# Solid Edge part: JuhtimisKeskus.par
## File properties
Author: Egon 815
Template: Normal.par
Last saved by: Egon 815
Revision: 6
Application: Solid Edge
Accuracy: 0,990
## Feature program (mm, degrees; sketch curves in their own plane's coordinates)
sketch for "unnamed Protrusion 1" plane through (0, 0, 10563.589) normal (0, 0, 1) x-axis (1, 0, 0)
  arc centre (50312.6386, -44736.8538) radius 46315.7343 from (4900.7754, -35631.365) to (8107.6748, -25660.9979) cw
  arc centre (2089.3841, -22290.9852) radius 6897.5945 from (8107.6748, -25660.9979) to (8107.6748, -18920.9725) ccw
  line (8107.6748, -13839.988) -> (8107.6748, -18920.9725)
  line (8107.6748, -13839.988) -> (0, -13839.988)
  line (-8107.6748, -13839.988) -> (0, -13839.988)
  line (-8107.6748, -18920.9725) -> (-8107.6748, -13839.988)
  arc centre (-2089.3841, -22290.9852) radius 6897.5945 from (-8107.6748, -25660.9979) to (-8107.6748, -18920.9725) cw
  arc centre (-50312.6386, -44736.8538) radius 46315.7343 from (-4900.7754, -35631.365) to (-8107.6748, -25660.9979) ccw
  arc centre (60.6073, -34547.8525) radius 5078.3183 from (-4900.7754, -35631.365) to (0, -39625.8092) ccw
  arc centre (-60.6073, -34547.8525) radius 5078.3183 from (4900.7754, -35631.365) to (0, -39625.8092) cw
extrude "unnamed Protrusion 1" add to key point along +normal
sketch for "unnamed Protrusion 2" plane through (0, -26732.8986, 13000.7205) normal (0, 0, 1) x-axis (1, 0, 0)
  circle centre (0, -8026.2647) radius 4634.2784
extrude "unnamed Protrusion 2" add to key point along +normal
sketch for "unnamed Protrusion 3" plane through (0, -34759.1633, 17243.6107) normal (0, 0, 1) x-axis (0, 1, 0)
  line (-4971.8461, -5486.8125) -> (2928.4356, -5486.8125)
  line (5915.7039, -5486.8125) -> (2928.4356, -5486.8125)
  line (5915.7039, 0) -> (5915.7039, -5486.8125)
  line (5915.7039, 0) -> (5915.7039, 5486.8125)
  line (5915.7039, 5486.8125) -> (2928.4356, 5486.8125)
  line (-4971.8461, 5486.8125) -> (2928.4356, 5486.8125)
  line (-6335.4528, 3406.3628) -> (-4971.8461, 5486.8125)
  line (-6335.4528, 0) -> (-6335.4528, 3406.3628)
  line (-6335.4528, 0) -> (-6335.4528, -3406.3628)
  line (-6335.4528, -3406.3628) -> (-4971.8461, -5486.8125)
extrude "unnamed Protrusion 3" add to key point along +normal
sketch for "unnamed Protrusion 4" plane through (0, -34969.0377, 22633.8218) normal (0, 0, 1) x-axis (0, 1, 0)
  circle centre (3866.8289, 0) radius 993.7379
extrude "unnamed Protrusion 4" add to key point along +normal
sketch for "unnamed Protrusion 5" plane through (0, -34969.0377, 22633.8218) normal (0, 0, 1) x-axis (0, 1, 0)
  arc centre (-838.8517, 156.2684) radius 1969.9228 from (-838.8517, 2126.1912) to (-2802.6619, 311.3349) ccw
  line (-2802.6619, 0) -> (-2802.6619, 311.3349)
  line (-2802.6619, 0) -> (-2802.6619, -311.3349)
  arc centre (-838.8517, -156.2684) radius 1969.9228 from (-838.8517, -2126.1912) to (-2802.6619, -311.3349) cw
  line (-838.8517, -2126.1912) -> (1157.986, -2126.1912)
  line (1157.986, -2126.1912) -> (1157.986, 0)
  line (1157.986, 2126.1912) -> (1157.986, 0)
  line (-838.8517, 2126.1912) -> (1157.986, 2126.1912)
extrude "unnamed Protrusion 5" add to key point along +normal
chamfer "unnamed Chamfer 1"
lofted protrusion "unnamed LoftedProtrusion 1"
chamfer "Chamfer_2" setback 500
chamfer "Chamfer_3" setback 100
chamfer "Chamfer_4" setback 100
chamfer "Chamfer_5" setback 100
chamfer "Chamfer_6" setback 500
chamfer "Chamfer_7" setback 500
chamfer "Chamfer_8" setback 500
logasc func "Lip_Groove_1"  LipOrGrooveWidth = 60 mm; LipOrGrooveHeight = 1000 mm
sketch for "ExtrudedProtrusion_6" plane through (0, -31102.2088, 30853.7571) normal (0, 0, 1) x-axis (0, 1, 0)
  arc centre (-4395.8563, 11697.9012) radius 9102.8237 from (-4402.7394, 2595.0801) to (1141.8911, 4473.3075) ccw
  arc centre (961.8585, 0) radius 4476.9288 from (1141.8911, 4473.3075) to (1141.8911, -4473.3075) cw
  arc centre (-4395.8563, -11697.9012) radius 9102.8237 from (-4402.7394, -2595.0801) to (1141.8911, -4473.3075) cw
  arc centre (-4402.7394, 0) radius 2595.0801 from (-6997.8195, 0) to (-4402.7394, -2595.0801) ccw
extrude "ExtrudedProtrusion_6" add finite 60 along +normal
logasc func "Lip_Groove_4"  LipOrGrooveWidth = 60 mm; LipOrGrooveHeight = 1000 mm
sketch for "unnamed RevolvedProtrusion 1" plane through (0, 0, 0) normal (1, 0, 0) x-axis (0, 1, 0)
  arc centre (-27564.0235, 39353.1178) radius 6027.8587 from (-30944.9145, 34362.6613) to (-26080.3504, 33510.7044) ccw
  line (-26080.3504, 33510.7044) -> (-26080.3504, 33411.8659)
  arc centre (-27553.9133, 39428.8527) radius 6194.7976 from (-31012.9057, 34289.7001) to (-26080.3504, 33411.8659) ccw
  line (-30944.9145, 34362.6613) -> (-31012.9057, 34289.7001)
revolve "unnamed RevolvedProtrusion 1" add finite 360 deg
web network "WebNetwork_1"  Thickness = 0.25 mm
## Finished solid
Body 1: solid body, 99 faces, 233 edges, 141 vertices, 1 internal void.
  Faces by surface: plane 54, cylinder 26, cone 8, spline 8, torus 3
  Edges by curve: line 129, circle 63, curve on surface 29, intersection 10, ellipse 1, spline 1
Bounding box of the edges (mm; curved faces can reach further): 17973.957 x 27254.628 x 28591.551, from (-8986.9785, -41094.6161, 10563.589) to (8986.9785, -13839.988, 39155.1399).
Cylindrical faces by radius (mm): R249.875 x1, R250.125 x1, R993.7379 x1, R1969.9228 x2, R2535.0801 x1, R2595.0801 x1, R4416.9288 x1, R4476.9288 x1, R4634.2784 x1, R5018.3183 x2, R5078.3183 x2, R6837.5945 x2, R6897.5945 x2, R9102.8237 x2, R9162.8237 x2, R46315.7343 x2, R46375.7343 x2
Conical faces (half-angle, radius in mm at the cone's reference point): 42.9806 deg R4139.6619 x1, 45 deg R1093.7379 x1, 45 deg R1969.9228 x2, 45 deg R4634.2784 x1, 45 deg R5134.2784 x3
Toroidal faces (ring radius, tube radius in mm): R-973.076 r6194.7976 x2, R-928.8401 r6027.8587 x1
Planar faces by outward normal: +x 4, +y 3, +z 7, -x 4, -y 3, -z 5, oblique 28
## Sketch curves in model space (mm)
circle centre (0, -29017.8119, 30913.7571) radius 250
line (0, -26080.3504, 33510.7044) -> (0, -26080.3504, 33411.8659)
arc centre (0, -27553.9133, 39428.8527) radius 6194.7976 from (0, -31012.9057, 34289.7001) through (0, -28639.3307, 33329.8867) to (0, -26080.3504, 33411.8659)
line (0, -30944.9145, 34362.6613) -> (0, -31012.9057, 34289.7001)
arc centre (0, -27564.0235, 39353.1178) radius 6027.8587 from (0, -30944.9145, 34362.6613) through (0, -28603.8872, 33415.6298) to (0, -26080.3504, 33510.7044)
arc centre (-11697.9012, -35498.0651, 30853.7571) radius 9102.8237 from (-2595.0801, -35504.9482, 30853.7571) through (-3076.3091, -32577.5259, 30853.7571) to (-4473.3075, -29960.3177, 30853.7571)
arc centre (0, -30140.3503, 30853.7571) radius 4476.9288 from (-4473.3075, -29960.3177, 30853.7571) through (263.3964, -25671.1766, 30853.7571) to (4473.3075, -29960.3177, 30853.7571)
arc centre (11697.9012, -35498.0651, 30853.7571) radius 9102.8237 from (2595.0801, -35504.9482, 30853.7571) through (3076.3091, -32577.5259, 30853.7571) to (4473.3075, -29960.3177, 30853.7571)
arc centre (0, -35504.9482, 30853.7571) radius 2595.0801 from (0, -38100.0283, 30853.7571) through (1887.5928, -37285.8002, 30853.7571) to (2595.0801, -35504.9482, 30853.7571)
arc centre (0, -35504.9482, 30853.7571) radius 2595.0801 from (0, -38100.0283, 30853.7571) through (-1887.5928, -37285.8002, 30853.7571) to (-2595.0801, -35504.9482, 30853.7571)
line (0, -37464.9383, 30853.7571) -> (1920.1047, -37464.9383, 30853.7571)
line (0, -36553.8811, 30853.7571) -> (2354.4419, -36553.8811, 30853.7571)
line (0, -26589.1925, 30853.7571) -> (2345.2536, -26589.1925, 30853.7571)
line (1623.0423, -35623.699, 30853.7571) -> (1930.069, -35623.699, 30853.7571)
arc centre (-86.6061, -34579.2579, 30853.7571) radius 2003.4357 from (1623.0423, -35623.699, 30853.7571) through (931.0643, -36304.9756, 30853.7571) to (0, -36580.8208, 30853.7571)
arc centre (86.6061, -34579.2579, 30853.7571) radius 2003.4357 from (-1623.0423, -35623.699, 30853.7571) through (-931.0643, -36304.9756, 30853.7571) to (0, -36580.8208, 30853.7571)
line (-1623.0423, -35623.699, 30853.7571) -> (-1930.069, -35623.699, 30853.7571)
arc centre (-141.854, -35623.699, 30853.7571) radius 1788.215 from (-1930.069, -35623.699, 30853.7571) through (-1418.3424, -36876.013, 30853.7571) to (-282.6171, -37406.3652, 30853.7571)
line (-282.6171, -37406.3652, 30853.7571) -> (282.6171, -37406.3652, 30853.7571)
arc centre (141.854, -35623.699, 30853.7571) radius 1788.215 from (282.6171, -37406.3652, 30853.7571) through (1490.7635, -36797.648, 30853.7571) to (1930.069, -35623.699, 30853.7571)
arc centre (156.2684, -35807.8895, 25923.1734) radius 1969.9228 from (311.3349, -37771.6996, 25923.1734) through (1642.246, -37101.1281, 25923.1734) to (2126.1912, -35807.8895, 25923.1734)
line (1787.9662, -35807.8895, 25923.1734) -> (2126.1912, -35807.8895, 25923.1734)
arc centre (-95.4064, -34657.3185, 25923.1734) radius 2207.013 from (1787.9662, -35807.8895, 25923.1734) through (1025.6736, -36558.3934, 25923.1734) to (0, -36862.2683, 25923.1734)
arc centre (95.4064, -34657.3185, 25923.1734) radius 2207.013 from (-1787.9662, -35807.8895, 25923.1734) through (-1025.6736, -36558.3934, 25923.1734) to (0, -36862.2683, 25923.1734)
line (-1787.9662, -35807.8895, 25923.1734) -> (-2126.1912, -35807.8895, 25923.1734)
arc centre (-156.2684, -35807.8895, 25923.1734) radius 1969.9228 from (-2126.1912, -35807.8895, 25923.1734) through (-1562.4659, -37187.4561, 25923.1734) to (-311.3349, -37771.6996, 25923.1734)
line (-311.3349, -37771.6996, 25923.1734) -> (311.3349, -37771.6996, 25923.1734)
arc centre (156.2684, -35807.8895, 22633.8218) radius 1969.9228 from (2126.1912, -35807.8895, 22633.8218) through (1562.4659, -37187.4561, 22633.8218) to (311.3349, -37771.6996, 22633.8218)
line (2126.1912, -35807.8895, 22633.8218) -> (2126.1912, -33811.0517, 22633.8218)
line (2126.1912, -33811.0517, 22633.8218) -> (0, -33811.0517, 22633.8218)
line (-2126.1912, -33811.0517, 22633.8218) -> (0, -33811.0517, 22633.8218)
line (-2126.1912, -35807.8895, 22633.8218) -> (-2126.1912, -33811.0517, 22633.8218)
arc centre (-156.2684, -35807.8895, 22633.8218) radius 1969.9228 from (-2126.1912, -35807.8895, 22633.8218) through (-1562.4659, -37187.4561, 22633.8218) to (-311.3349, -37771.6996, 22633.8218)
line (0, -37771.6996, 22633.8218) -> (-311.3349, -37771.6996, 22633.8218)
line (0, -37771.6996, 22633.8218) -> (311.3349, -37771.6996, 22633.8218)
circle centre (0, -31102.2088, 22633.8218) radius 993.7379
line (3406.3628, -41094.6161, 17243.6107) -> (5486.8125, -39731.0094, 17243.6107)
line (5486.8125, -39731.0094, 17243.6107) -> (5486.8125, -31830.7277, 17243.6107)
line (5486.8125, -28843.4594, 17243.6107) -> (5486.8125, -31830.7277, 17243.6107)
line (0, -28843.4594, 17243.6107) -> (5486.8125, -28843.4594, 17243.6107)
line (0, -28843.4594, 17243.6107) -> (-5486.8125, -28843.4594, 17243.6107)
line (-5486.8125, -28843.4594, 17243.6107) -> (-5486.8125, -31830.7277, 17243.6107)
line (-5486.8125, -39731.0094, 17243.6107) -> (-5486.8125, -31830.7277, 17243.6107)
line (-3406.3628, -41094.6161, 17243.6107) -> (-5486.8125, -39731.0094, 17243.6107)
line (0, -41094.6161, 17243.6107) -> (-3406.3628, -41094.6161, 17243.6107)
line (0, -41094.6161, 17243.6107) -> (3406.3628, -41094.6161, 17243.6107)
circle centre (0, -34759.1633, 13000.7205) radius 4634.2784
arc centre (60.6073, -34547.8525, 10563.589) radius 5078.3183 from (-4900.7754, -35631.365, 10563.589) through (-3031.4665, -38576.301, 10563.589) to (0, -39625.8092, 10563.589)
arc centre (-50312.6386, -44736.8538, 10563.589) radius 46315.7343 from (-4900.7754, -35631.365, 10563.589) through (-6221.4927, -30555.2426, 10563.589) to (-8107.6748, -25660.9979, 10563.589)
arc centre (-2089.3841, -22290.9852, 10563.589) radius 6897.5945 from (-8107.6748, -25660.9979, 10563.589) through (-8986.9785, -22290.9852, 10563.589) to (-8107.6748, -18920.9725, 10563.589)
line (-8107.6748, -18920.9725, 10563.589) -> (-8107.6748, -13839.988, 10563.589)
line (-8107.6748, -13839.988, 10563.589) -> (0, -13839.988, 10563.589)
line (8107.6748, -13839.988, 10563.589) -> (0, -13839.988, 10563.589)
line (8107.6748, -13839.988, 10563.589) -> (8107.6748, -18920.9725, 10563.589)
arc centre (2089.3841, -22290.9852, 10563.589) radius 6897.5945 from (8107.6748, -25660.9979, 10563.589) through (8986.9785, -22290.9852, 10563.589) to (8107.6748, -18920.9725, 10563.589)
arc centre (50312.6386, -44736.8538, 10563.589) radius 46315.7343 from (4900.7754, -35631.365, 10563.589) through (6221.4927, -30555.2426, 10563.589) to (8107.6748, -25660.9979, 10563.589)
arc centre (-60.6073, -34547.8525, 10563.589) radius 5078.3183 from (4900.7754, -35631.365, 10563.589) through (3031.4665, -38576.301, 10563.589) to (0, -39625.8092, 10563.589)
line (-4658.2982, 0, 17061.7126) -> (-4658.2982, 0, 22614.5062)
line (-4658.2982, 0, 22614.5062) -> (4630.011, 0, 22614.5062)
line (4630.011, 0, 22614.5062) -> (4630.011, 0, 17061.7126)
line (4630.011, 0, 17061.7126) -> (-4658.2982, 0, 17061.7126)
line (-2437.1808, 0, 27536.3004) -> (2358.4137, 0, 27536.3004)
line (2358.4137, 0, 27536.3004) -> (2358.4137, 0, 22614.5062)
line (-2437.1808, 0, 22614.5062) -> (2358.4137, 0, 22614.5062)
line (-2437.1808, 0, 22614.5062) -> (-2437.1808, 0, 27536.3004)
line (-1478.0619, 0, 31221.3362) -> (1575.9746, 0, 31221.3362)
line (1575.9746, 0, 31221.3362) -> (1575.9746, 0, 27536.3004)
line (-1478.0619, 0, 27536.3004) -> (1575.9746, 0, 27536.3004)
line (-1478.0619, 0, 27536.3004) -> (-1478.0619, 0, 31221.3362)
line (0, -36553.8811, 30853.7571) -> (0, -36553.8811, 25923.1734)
line (0, -37771.6996, 22633.8218) -> (0, -37771.6996, 25923.1734)
line (0, -37464.9383, 30853.7571) -> (0, -37771.6996, 25923.1734)
line (0, -28843.4594, 17243.6107) -> (0, -28843.4594, 10563.589)
line (0, -39625.8092, 17243.6107) -> (0, -28843.4594, 17243.6107)
line (0, -28843.4594, 10563.589) -> (0, -39625.8092, 10563.589)
line (0, -39625.8092, 10563.589) -> (0, -39625.8092, 17243.6107)
line (0, -28843.4594, 13000.7205) -> (0, -28843.4594, 10563.589)
line (0, -13839.988, 10563.589) -> (0, -28843.4594, 10563.589)
line (0, -13839.988, 13000.7205) -> (0, -13839.988, 10563.589)
line (0, -13839.988, 13000.7205) -> (0, -28843.4594, 13000.7205)
line (0, -31830.7277, 22633.8218) -> (0, -31830.7277, 17243.6107)
line (0, -41094.6161, 22633.8218) -> (0, -31830.7277, 22633.8218)
line (0, -41094.6161, 17243.6107) -> (0, -41094.6161, 22633.8218)
line (0, -35690.6812, 17243.6107) -> (0, -41094.6161, 17243.6107)
line (0, -33811.0517, 25923.1734) -> (0, -33811.0517, 22633.8218)
line (0, -37771.6996, 25923.1734) -> (0, -33811.0517, 25923.1734)
line (0, -29834.8339, 30853.7571) -> (0, -31827.7717, 30853.7571)
line (0, -31827.7717, 30853.7571) -> (0, -31827.7717, 17243.6107)
line (0, -31827.7717, 17243.6107) -> (0, -29834.8339, 17243.6107)
line (0, -29834.8339, 17243.6107) -> (0, -29834.8339, 30853.7571)
line (0, -37464.9383, 30853.7571) -> (0, -37464.9383, 31353.7571)
line (0, -37464.9383, 31353.7571) -> (0, -26589.1925, 31353.7571)
line (0, -26589.1925, 31353.7571) -> (0, -26589.1925, 30853.7571)
line (0, -26589.1925, 30853.7571) -> (0, -37464.9383, 30853.7571)
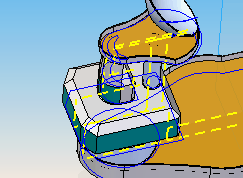
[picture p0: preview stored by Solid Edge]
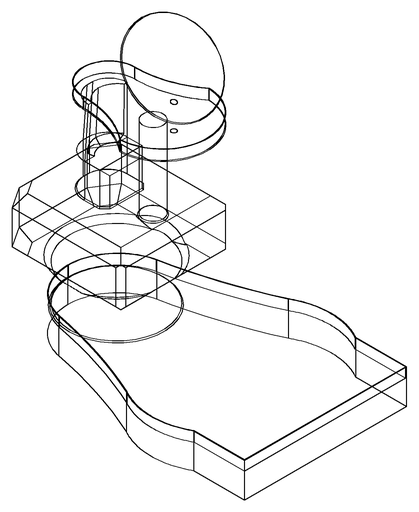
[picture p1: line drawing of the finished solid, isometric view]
